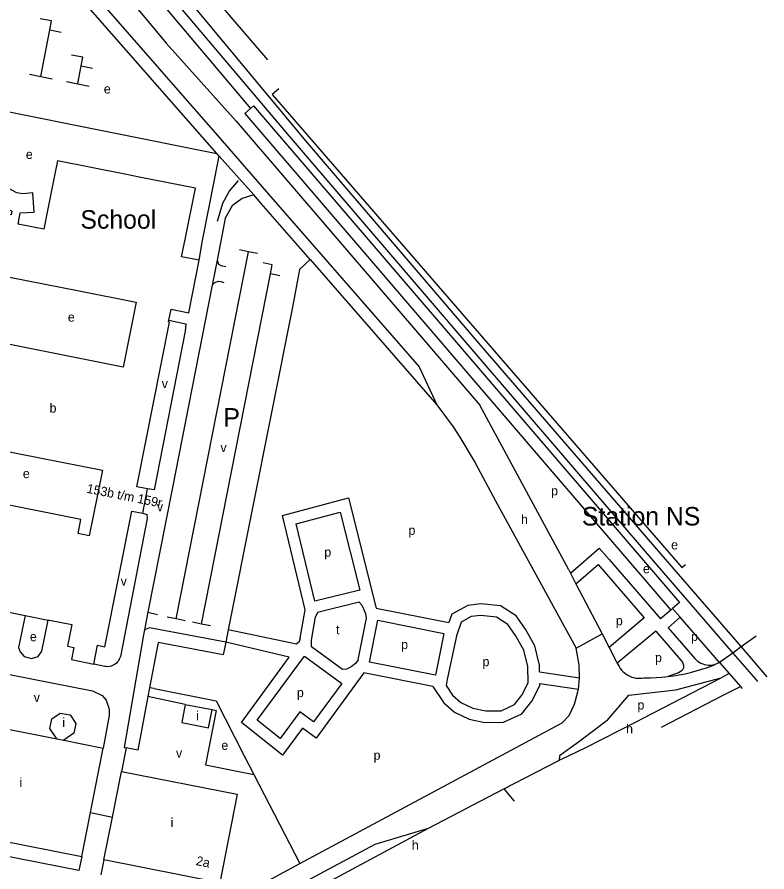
# Model space of a CAD drawing. Extents: x 158356 to 159894, y 383831 to 385260.
# Drawn here: x 159570.1 to 159893.9, y 384449.8 to 384819.2 of the extents above; entities that cross this region are included whole.
import ezdxf

# ---------------------------------------------------------------- set-up
doc = ezdxf.new("R2010")
doc.units = 0
for name, color, linetype in [('BLT_Basislijn', 7, 'Continuous'), ('BLT_Bebouwing', 7, 'Continuous'), ('BLT_Bebouwing_beschrifting', 7, 'Continuous'), ('BLT_Centroide', 7, 'Continuous'), ('BLT_Huisnummer', 7, 'Continuous'), ('BLT_Huisnummer_reeks', 7, 'Continuous'), ('BLT_Onderverdeling_panden', 7, 'Continuous'), ('BLT_Spoorlijn', 7, 'Continuous'), ('BLT_Tekst_parkeren', 7, 'Continuous'), ('BLT_Vlakafsluiter', 7, 'Continuous')]:
    doc.layers.add(name, color=color, linetype=linetype)

msp = doc.modelspace()

# ---------------------------------------------------------------- linework, layer by layer
at = {"layer": 'BLT_Basislijn'}
for p, q in [((159599.4, 384850.02), (159634.55, 384807.95)), ((159590.89, 384843.45), (159658.67, 384765.63)), ((159580.34, 384793.51), (159584.26, 384813.6)), ((159584.26, 384813.6), (159589.17, 384812.64)), ((159634.55, 384807.95), (159664.67, 384774.26)), ((159596.29, 384790.33), (159597.82, 384798.13)), ((159597.82, 384798.13), (159602.72, 384797.17)), ((159575.43, 384794.46), (159580.34, 384793.51)), ((159580.34, 384793.51), (159585.24, 384792.55)), ((159591.38, 384791.29), (159596.29, 384790.33)), ((159596.29, 384790.33), (159601.2, 384789.37)), ((159683.11, 384788.1), (159680.31, 384785.73)), ((159680.31, 384785.73), (159857.26, 384581.26)), ((159554.98, 384780.49), (159656.42, 384760.21)), ((159670.94, 384779.64), (159668.46, 384777.52)), ((159672.26, 384780.77), (159670.94, 384779.64)), ((159672.26, 384780.77), (159856.21, 384566.23)), ((159668.46, 384777.52), (159852.43, 384562.95)), ((159664.67, 384774.26), (159770.01, 384651.4)), ((159658.67, 384765.63), (159678.64, 384742.72)), ((159657.37, 384759.13), (159656.42, 384760.21)), ((159656.93, 384756.88), (159657.37, 384759.13)), ((159672.34, 384742.3), (159657.37, 384759.13)), ((159675.47, 384738.68), (159672.34, 384742.3)), ((159678.64, 384742.72), (159743.7, 384668.1)), ((159696.67, 384714.43), (159675.47, 384738.68)), ((159659.29, 384728.32), (159656.49, 384714.08)), ((159638.79, 384559.11), (159670.04, 384717.8)), ((159670.04, 384717.8), (159666.12, 384718.57)), ((159673.96, 384717.03), (159670.04, 384717.8)), ((159656.49, 384714.08), (159654.36, 384703.29)), ((159692.04, 384710.14), (159696.67, 384714.43)), ((159649.75, 384556.89), (159679.56, 384708.23)), ((159683.62, 384707.43), (159679.56, 384708.23)), ((159808.38, 384580.34), (159770.01, 384651.4)), ((159684.68, 384603.78), (159713.22, 384611.39)), ((159713.22, 384611.39), (159725.22, 384563.73)), ((159690.68, 384600.21), (159709.61, 384605.25)), ((159709.61, 384605.25), (159718.11, 384571.46)), ((159694.51, 384563.06), (159684.68, 384603.78)), ((159698.76, 384566.78), (159690.68, 384600.21)), ((159809.13, 384578.86), (159821.52, 384589.66)), ((159821.52, 384589.66), (159825.78, 384584.8)), ((159825.78, 384584.8), (159847.98, 384559.09)), ((159808.38, 384580.34), (159809.13, 384578.86)), ((159811.47, 384574.26), (159821.05, 384582.62)), ((159821.05, 384582.62), (159840.99, 384559.54)), ((159857.26, 384581.26), (159858.84, 384582.61)), ((159809.13, 384578.86), (159811.47, 384574.26)), ((159811.47, 384574.26), (159822.75, 384552.68)), ((159718.11, 384571.46), (159698.76, 384566.78)), ((159717.91, 384566.27), (159699.79, 384561.89)), ((159856.21, 384566.23), (159853.24, 384563.65)), ((159626.62, 384561.96), (159625.14, 384554.39)), ((159626.62, 384561.96), (159630.81, 384561)), ((159692.3, 384550.85), (159694.51, 384563.06)), ((159699.79, 384561.89), (159699.05, 384560.06)), ((159725.22, 384563.73), (159756.58, 384557.5)), ((159853.24, 384563.65), (159852.43, 384562.95)), ((159856.51, 384559.87), (159853.24, 384563.65)), ((159638.79, 384559.11), (159634.87, 384559.88)), ((159642.71, 384558.33), (159638.79, 384559.11)), ((159649.75, 384556.89), (159645.83, 384557.66)), ((159653.67, 384556.12), (159649.75, 384556.89)), ((159662.09, 384558.77), (159661.25, 384554.33)), ((159697.22, 384549.96), (159699.05, 384560.06)), ((159717.35, 384541.38), (159720.95, 384559.48)), ((159722.26, 384540.4), (159725.85, 384558.51)), ((159725.85, 384558.51), (159754.38, 384552.84)), ((159840.99, 384559.54), (159825.85, 384546.74)), ((159661.25, 384554.33), (159660.24, 384549.06)), ((159845.99, 384553.76), (159829.35, 384540.04)), ((159851.25, 384555.31), (159862.77, 384541.98)), ((159697.26, 384547.01), (159697.22, 384549.96)), ((159754.38, 384552.84), (159750.78, 384534.74)), ((159822.75, 384552.68), (159825.85, 384546.74)), ((159687.68, 384542.57), (159660.24, 384549.06)), ((159710.62, 384537.2), (159697.26, 384547.01)), ((159825.85, 384546.74), (159829.35, 384540.04)), ((159666.96, 384514.37), (159687.68, 384542.57)), ((159673.84, 384515.28), (159694.23, 384543.04)), ((159694.23, 384543.04), (159710.33, 384531.21)), ((159608.02, 384538.55), (159603.32, 384539.51)), ((159750.78, 384534.74), (159722.26, 384540.4)), ((159829.35, 384540.04), (159830.15, 384538.49)), ((159873.54, 384540.23), (159871.26, 384539.28)), ((159873.54, 384540.23), (159877.62, 384535.52)), ((159719.89, 384535.77), (159699.21, 384507.63)), ((159749.6, 384529.88), (159719.89, 384535.77)), ((159795.76, 384536.25), (159813.07, 384533.68)), ((159877.62, 384535.52), (159882.5, 384529.89)), ((159710.33, 384531.21), (159698.14, 384514.62)), ((159795.87, 384531.18), (159812.52, 384528.7)), ((159812.52, 384528.7), (159813.07, 384533.68)), ((159840.53, 384516.2), (159874.13, 384533.7)), ((159627.3, 384529.35), (159626.52, 384525.61)), ((159629.33, 384528.96), (159627.3, 384529.35)), ((159882.5, 384529.89), (159883.3, 384528.96)), ((159692.26, 384518.94), (159683.77, 384507.39)), ((159698.14, 384514.62), (159692.26, 384518.94)), ((159684.72, 384500.24), (159666.96, 384514.37)), ((159683.77, 384507.39), (159673.84, 384515.28)), ((159693.33, 384511.95), (159684.72, 384500.24)), ((159699.21, 384507.63), (159693.33, 384511.95)), ((159617.26, 384503.35), (159615.17, 384493.22)), ((159668.23, 384500), (159672.4, 384491.9)), ((159803.73, 384497.83), (159804.27, 384498.09)), ((159804.27, 384498.09), (159808.31, 384500)), ((159804.32, 384500), (159804.27, 384498.09)), ((159672.4, 384491.9), (159692.25, 384453.39)), ((159601.78, 384475.51), (159611.26, 384473.48)), ((159596.78, 384450.34), (159526.37, 384464.28)), ((159598.04, 384456.49), (159596.78, 384450.34)), ((159607.6, 384454.94), (159606.33, 384448.55)), ((159662.53, 384437.45), (159692.25, 384453.39))]:
    msp.add_line(p, q, dxfattribs=at)
for points in [[(159579.89, 384888.43), (159615.45, 384845.5), (159670.94, 384779.64)], [(159656.42, 384760.21), (159597.62, 384827.42), (159588.53, 384833.9), (159579.93, 384843.97)], [(159584.26, 384813.6), (159585.03, 384817.53), (159580.12, 384818.48)], [(159597.82, 384798.13), (159598.54, 384801.82), (159593.63, 384802.78)], [(159648.75, 384714.13), (159650.18, 384722.56), (159653.01, 384737.11), (159656.93, 384756.88)], [(159656.6, 384731.02), (159658.91, 384738.75), (159661.67, 384743.82), (159665.68, 384748.59)], [(159672.34, 384742.3), (159667.26, 384740.73), (159662.95, 384737.67), (159660.04, 384732.25), (159659.29, 384728.32)], [(159656.49, 384714.08), (159657.08, 384712.47), (159658.1, 384711.81), (159660.31, 384711.35)], [(159679.56, 384708.23), (159680.32, 384712.14), (159676.4, 384712.91)], [(159696.67, 384714.43), (159751.46, 384651.58)], [(159692.04, 384710.14), (159689.01, 384693.8), (159662.09, 384558.77)], [(159654.36, 384703.29), (159655.57, 384704.46), (159657.06, 384704.99), (159658.1, 384704.85), (159659.33, 384704.52)], [(159654.36, 384703.29), (159637.02, 384615.17), (159626.62, 384561.96)], [(159635.66, 384688.16), (159643.01, 384686.58), (159642.76, 384683.41), (159629.26, 384614.94), (159626.44, 384615.31)], [(159743.7, 384668.1), (159751.46, 384651.58)], [(159751.46, 384651.58), (159758.4, 384642.11), (159761.33, 384637.66), (159767.91, 384626.56), (159776.76, 384610.2), (159811.58, 384546.39)], [(159624.35, 384604.75), (159626.07, 384604.27), (159626.28, 384602.52), (159614.74, 384542.92)], [(159720.95, 384559.48), (159720.66, 384561.31), (159719.92, 384563.34), (159719.13, 384564.9), (159717.91, 384566.27)], [(159795.76, 384536.25), (159795.7, 384539.17), (159793.65, 384547.44), (159789.63, 384554.62), (159785.6, 384560.39), (159778.88, 384564.73), (159770.41, 384565.64), (159764.72, 384564.96), (159757.89, 384561.19), (159756.58, 384557.5)], [(159573.58, 384560.59), (159570.73, 384546.76), (159571.48, 384544.86), (159573.13, 384542.9), (159576.29, 384541.94), (159579.25, 384542.9), (159580.76, 384545.21), (159583.47, 384558.62)], [(159852.43, 384562.95), (159847.98, 384559.09)], [(159856.51, 384559.87), (159851.25, 384555.31)], [(159873.54, 384540.23), (159856.51, 384559.87)], [(159553.62, 384554.38), (159557.99, 384551.6), (159560.42, 384546.76), (159560.9, 384541.51), (159562.53, 384536.39), (159566.87, 384535.08), (159602.74, 384528.02), (159606.87, 384526.05), (159608.63, 384523.94), (159609.83, 384520.08), (159609.82, 384517.39), (159607.25, 384503.27)], [(159625.14, 384554.39), (159624.73, 384552.25), (159616.37, 384503.52), (159617.26, 384503.35)], [(159660.24, 384549.06), (159627.24, 384555.26), (159625.14, 384554.39)], [(159692.3, 384550.85), (159691.98, 384549.23), (159690.82, 384548.12), (159661.25, 384554.33)], [(159845.99, 384553.76), (159857.46, 384540.48), (159857.93, 384539.17), (159857.93, 384538.03), (159857.35, 384536.86), (159855.82, 384535.79), (159851.14, 384534.2)], [(159660.24, 384549.06), (159659.18, 384543.51), (159631.04, 384548.88), (159627.3, 384529.35)], [(159813.07, 384533.68), (159812.87, 384539.32), (159811.58, 384546.39)], [(159614.74, 384542.92), (159614.54, 384542.26), (159614.26, 384541.64), (159613.92, 384541.05), (159613.5, 384540.5), (159613.03, 384540.01), (159612.5, 384539.58), (159611.93, 384539.21), (159611.31, 384538.91), (159610.67, 384538.68), (159610, 384538.53), (159609.32, 384538.46), (159608.64, 384538.47), (159608.02, 384538.55)], [(159717.35, 384541.38), (159716.25, 384539.78), (159714.39, 384538.34)], [(159830.15, 384538.49), (159830.63, 384537.74), (159831.18, 384537.02), (159831.78, 384536.36), (159832.45, 384535.76), (159833.16, 384535.22), (159833.92, 384534.74), (159834.71, 384534.33), (159835.55, 384534), (159836.4, 384533.74), (159837.28, 384533.55), (159838.17, 384533.45), (159839.07, 384533.43), (159839.96, 384533.49), (159840.85, 384533.62), (159841.12, 384533.68)], [(159851.14, 384534.2), (159853.63, 384534.53), (159856.11, 384534.94), (159858.58, 384535.42), (159861.02, 384535.99), (159863.45, 384536.63), (159865.86, 384537.35), (159868.24, 384538.15), (159870.6, 384539.02), (159871.26, 384539.28)], [(159862.77, 384541.98), (159863.37, 384541.39), (159864.02, 384540.86), (159864.73, 384540.39), (159865.47, 384540), (159866.25, 384539.67), (159867.05, 384539.42), (159867.88, 384539.25), (159868.72, 384539.16), (159869.56, 384539.15), (159870.4, 384539.21), (159871.26, 384539.28)], [(159714.39, 384538.34), (159712.44, 384537.44), (159710.62, 384537.2)], [(159877.62, 384535.52), (159874.13, 384533.7)], [(159749.6, 384529.88), (159754.4, 384522.84), (159759.04, 384518.84), (159765.33, 384515.73), (159772.09, 384514.38), (159780.23, 384514.42), (159788.12, 384518.11), (159792.38, 384523.49), (159795.89, 384530.33), (159795.87, 384531.18)], [(159824.94, 384515.16), (159834.33, 384526.08), (159854.64, 384528.4), (159874.13, 384533.7)], [(159841.12, 384533.68), (159843.63, 384533.69), (159846.14, 384533.78), (159848.64, 384533.95), (159851.14, 384534.2)], [(159629.33, 384528.96), (159656.03, 384523.68), (159664.06, 384508.1)], [(159692.25, 384453.39), (159805.59, 384514.17), (159808.49, 384517.32), (159810.91, 384522.23), (159812.35, 384527.66), (159812.52, 384528.7)], [(159848.42, 384512.35), (159875, 384526.08), (159882.5, 384529.89)], [(159642.73, 384522.16), (159626.52, 384525.61), (159622.26, 384502.39), (159617.26, 384503.35)], [(159654.35, 384519.89), (159656.05, 384519.59), (159651.41, 384496.03), (159672.4, 384491.9)], [(159824.94, 384515.16), (159813.16, 384506.33), (159804.32, 384500)], [(159808.31, 384500), (159815.74, 384503.59), (159823.13, 384507.24), (159830.49, 384510.97), (159837.81, 384514.77), (159840.53, 384516.2)], [(159664.06, 384508.1), (159668.23, 384500)], [(159780.37, 384485.64), (159803.73, 384497.83)], [(159747.86, 384468.66), (159780.37, 384485.64)], [(159610.81, 384400.63), (159724.82, 384461.78), (159747.86, 384468.66)], [(159697.99, 384441.86), (159739.99, 384464.55), (159747.86, 384468.66)]]:
    msp.add_lwpolyline(points, dxfattribs=at)
msp.add_lwpolyline([(159759.84, 384551.76), (159755.89, 384532.87), (159755.36, 384530.31), (159758.16, 384526.2), (159761.82, 384523.04), (159766.96, 384520.5), (159772.58, 384519.38), (159779.11, 384519.41), (159784.93, 384522.14), (159788.15, 384526.21), (159790.87, 384531.49), (159790.71, 384538.51), (159788.95, 384545.58), (159785.39, 384551.96), (159782.06, 384556.72), (159777.17, 384559.89), (159770.44, 384560.61), (159766.28, 384560.11), (159761.97, 384557.73)], close=True, dxfattribs=at)
at = {"layer": 'BLT_Bebouwing'}
for p, q in [((159617.36, 384751.1), (159587.6, 384757.02)), ((159642.81, 384723.75), (159647.12, 384745.18)), ((159583.29, 384735.59), (159581.65, 384727.48)), ((159581.65, 384727.48), (159570.52, 384729.73)), ((159641.18, 384715.64), (159642.81, 384723.75)), ((159648.75, 384714.13), (159641.18, 384715.64)), ((159596.9, 384700.82), (159621.54, 384695.93)), ((159621.54, 384695.93), (159615.89, 384667.84)), ((159635.66, 384688.16), (159636.6, 384692.93)), ((159537.93, 384637.08), (159606.93, 384623.36)), ((159606.93, 384623.36), (159601.3, 384595)), ((159624.35, 384604.75), (159626.44, 384615.31)), ((159535.63, 384568.14), (159573.58, 384560.59)), ((159573.58, 384560.59), (159583.47, 384558.62)), ((159642.73, 384522.16), (159654.35, 384519.89)), ((159564.79, 384511.8), (159587.2, 384507.3)), ((159590.25, 384506.68), (159607.25, 384503.27)), ((159601.78, 384475.51), (159607.25, 384503.27)), ((159611.26, 384473.48), (159615.17, 384493.22)), ((159598.04, 384456.49), (159601.78, 384475.51)), ((159607.6, 384454.94), (159611.26, 384473.48)), ((159534.72, 384468.97), (159598.04, 384456.49))]:
    msp.add_line(p, q, dxfattribs=at)
for points in [[(159587.6, 384757.02), (159586.18, 384750), (159583.29, 384735.59)], [(159647.12, 384745.18), (159622.88, 384750), (159617.36, 384751.1)], [(159570.52, 384729.73), (159571.5, 384734.64), (159577.46, 384734.93), (159576.95, 384743.17), (159572.52, 384742.86), (159570.05, 384743.25), (159564.76, 384745.99), (159561.12, 384738.54), (159567.9, 384735.33), (159567.59, 384733.79), (159565.33, 384734.24), (159564.66, 384730.83)], [(159553.82, 384713.52), (159555.5, 384713.18), (159554.71, 384709.18), (159558.58, 384708.41), (159596.9, 384700.82)], [(159636.6, 384692.93), (159644.21, 384691.41), (159648.75, 384714.13)], [(159626.44, 384615.31), (159621.75, 384616.22), (159635.91, 384687.38), (159635.52, 384687.46), (159635.66, 384688.16)], [(159615.89, 384667.84), (159561.77, 384678.67), (159546.6, 384681.7)], [(159601.3, 384595), (159596.45, 384595.96), (159597.67, 384602.12), (159548.61, 384611.88), (159550.55, 384621.67), (159535.46, 384624.68)], [(159608.05, 384547.08), (159619.65, 384605.73), (159624.35, 384604.75)], [(159583.47, 384558.62), (159584.03, 384558.52), (159593.68, 384556.65)], [(159593.68, 384556.65), (159591.83, 384547.32), (159594.68, 384546.75), (159593.63, 384541.59), (159603.32, 384539.51)], [(159603.32, 384539.51), (159604.81, 384547.73), (159608.05, 384547.08)], [(159642.73, 384522.16), (159641.19, 384514.35), (159652.8, 384512.06), (159654.35, 384519.89)], [(159587.2, 384507.3), (159584.31, 384511.74), (159585.12, 384515.99), (159588.72, 384518.43), (159593.04, 384517.63)], [(159593.04, 384517.63), (159595.48, 384513.95), (159594.62, 384509.72), (159590.25, 384506.68)], [(159615.17, 384493.22), (159665.22, 384483.32), (159657.65, 384445.04), (159607.6, 384454.94)]]:
    msp.add_lwpolyline(points, dxfattribs=at)
at = {"layer": 'BLT_Onderverdeling_panden'}
msp.add_line((159587.2, 384507.3), (159590.25, 384506.68), dxfattribs=at)
at = {"layer": 'BLT_Spoorlijn'}
for p, q in [((159845.66, 384583.14), (159879.21, 384544.35)), ((159850.07, 384584.98), (159882.8, 384546.97)), ((159882.8, 384546.97), (159893.95, 384534.03))]:
    msp.add_line(p, q, dxfattribs=at)
for points in [[(159619.27, 384848.73), (159687.56, 384767.69)], [(159624.43, 384850.38), (159694.73, 384765.66)], [(159636.94, 384848.91), (159678.22, 384800.74)], [(159687.56, 384767.69), (159765.59, 384676.52)], [(159694.73, 384765.66), (159770.38, 384677.07)], [(159765.59, 384676.52), (159845.66, 384583.14)], [(159770.38, 384677.07), (159850.07, 384584.98)], [(159879.21, 384544.35), (159889.28, 384532.71), (159889.83, 384532.07)]]:
    msp.add_lwpolyline(points, dxfattribs=at)
at = {"layer": 'BLT_Vlakafsluiter'}
for p, q in [((159811.58, 384546.39), (159822.75, 384552.68)), ((159889.3, 384551.7), (159882.8, 384546.97)), ((159882.8, 384546.97), (159879.21, 384544.35)), ((159879.21, 384544.35), (159873.54, 384540.23)), ((159780.37, 384485.64), (159784.77, 384480.36))]:
    msp.add_line(p, q, dxfattribs=at)

# ---------------------------------------------------------------- texts
at = {"layer": 'BLT_Bebouwing_beschrifting'}
msp.add_text('School', height=8, rotation=359.9995, dxfattribs=at).set_placement((159597.46, 384727.74))
msp.add_text('Station NS', height=8, dxfattribs=at).set_placement((159814.06, 384599.47))
at = {"layer": 'BLT_Centroide'}
for s, p in [('e', (159607.56, 384786.16)), ('e', (159573.87, 384757.87)), ('e', (159592.02, 384687.55)), ('v', (159632.57, 384658.82)), ('b', (159584.14, 384648.25)), ('v', (159657.93, 384631.2)), ('e', (159572.59, 384619.95)), ('p', (159800.76, 384612.49)), ('h', (159787.76, 384600.13)), ('p', (159739.15, 384595.44)), ('e', (159852.58, 384589.14)), ('p', (159702.79, 384586.01)), ('e', (159840.39, 384578.81)), ('v', (159614.83, 384573.47)), ('p', (159828.73, 384556.36)), ('t', (159707.86, 384552.5)), ('e', (159575.64, 384549.45)), ('p', (159861.19, 384549.57)), ('p', (159735.97, 384546.05)), ('p', (159845.62, 384540.44)), ('p', (159771.14, 384538.67)), ('p', (159690.96, 384525.3)), ('p', (159838.05, 384519.94)), ('i', (159589.62, 384512.37)), ('i', (159647.44, 384515.3)), ('h', (159833.16, 384509.64)), ('e', (159658.32, 384502.5)), ('p', (159724.08, 384498.24)), ('i', (159571.12, 384486.5)), ('i', (159636.41, 384469.12)), ('h', (159740.6, 384459.4))]:
    msp.add_text(s, height=4, dxfattribs=at).set_placement(p)
for p in [(159630.54, 384605.56), (159577.32, 384523.19), (159638.77, 384499.14)]:
    msp.add_text('v', height=4, rotation=1, dxfattribs=at).set_placement(p)
at = {"layer": 'BLT_Huisnummer'}
msp.add_text('2a', height=4, rotation=348.8132, dxfattribs=at).set_placement((159647.13, 384452.76))
at = {"layer": 'BLT_Huisnummer_reeks'}
msp.add_text('153b t/m 159r', height=4, rotation=348.751, dxfattribs=at).set_placement((159599.93, 384613.65))
at = {"layer": 'BLT_Tekst_parkeren'}
msp.add_text('P', height=8, dxfattribs=at).set_placement((159659.22, 384642.18))

doc.saveas('drawing.dxf')
